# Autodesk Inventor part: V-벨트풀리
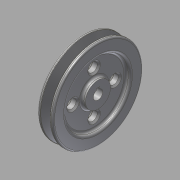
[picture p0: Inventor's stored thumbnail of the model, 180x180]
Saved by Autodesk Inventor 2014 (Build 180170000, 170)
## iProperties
Created: 2015-09
Part Number: V-벨트풀리
Material: 강철, 연강
Document SubType Name: Modeling
Designer: mduedu
Density: 1 g/cm^3
Appearance: Steel
Author: mduedu
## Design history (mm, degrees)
sketch "스케치1"
  geometry: L1 (-10, 0)-(10, 0); L2 (-10, 0)-(-10, 57.5); L3 (-10, 57.5)-(-6.062, 57.5); L4 (-6.062, 57.5)-(-2.001, 45); L5 (-2.001, 45)-(2.001, 45); L6 (2.001, 45)-(6.062, 57.5); L7 (6.062, 57.5)-(10, 57.5); L8 (10, 57.5)-(10, 0); L9 (0, 0)-(0, 45); L10 (-10, 53)-(10, 53); 3 further points
  constraints: 20 end point, 6 point on line, 3 perpendicular, 2 midpoint, 2 parallel, 2 symmetric about line, 1 coincident, 1 collinear, 1 equal length, 1 horizontal, 1 vertical, 1 vertical alignment
  dimensions: "d0" = 20 distance between parallel lines of L8 L2; "d2" = 115 diameter of L3 L1; "d5" = 8 distance between parallel lines of L5 L10; "d6" = 9.2 distance of point (4.6, 53) point (-4.6, 53); "d7" = 36 deg angle of L6 L4; "d40" = 4.5 distance between parallel lines of L10 L3
revolve "회전1" sketch "스케치1" stored, may be unused: angle "d8" = 90 deg
sketch "스케치2"
  geometry: C1 r 16 at (0, 0); C2 r 41 at (0, 0); 1 further point
  constraints: 2 centre point, 2 coincident
  dimensions: "d9" = 32 diameter of C1; "d41" = 82 diameter of C2
extrude "돌출5" cut sketch "스케치2" distance "d42" = 5; taper "d43" = 0 deg
hole "구멍2" diameter "d46" = 12; stored, may be unused: countersink angle "d50" = 90 deg, drill point angle "d52" = 118 deg; dims "d44" = 10, "d45" = 10, "d47" = 6, "d48" = 4, "d49" = 2, "d51" = 8
sketch "스케치8"
  geometry: L1 (-2, 5.657)-(2, 5.657); L2 (2, 5.657)-(2, 7.8); L3 (2, 7.8)-(-2, 7.8); L4 (-2, 7.8)-(-2, 5.657); A1 r 6 centre (0, 0) between (-2, 5.657) and (2, 5.657) reference; 1 further point
  constraints: 8 end point, 2 parallel, 2 point on circle, 1 horizontal, 1 perpendicular
  dimensions: "d53" = 4 distance of L2.end L3.end; "d55" = 13.8 dimension on A1 L3
extrude "돌출6" cut sketch "스케치8" stored distance "d56" = 5; taper "d57" = 0 deg
sketch "스케치9"
  geometry: C1 r 6 at (0, 27); 1 further point
  constraints: 1 centre point, 1 vertical alignment
  dimensions: "d61" = 12 diameter of C1; "d62" = 27 distance of C1.centre point (0, 0)
extrude "돌출7" cut sketch "스케치9" stored distance "d63" = 5; taper "d64" = 0 deg
chamfer "모따기3" distance "d65" = 2; stored, may be unused: second distance "d66" = 2, angle "d67" = 45 deg
fillet "모깎기5" dims "d71" = 2, "d72" = 1, "d73" = 0.5
fillet "모깎기6" dims "d74" = 3
fillet "모깎기7" dims "d75" = 3
fillet "모깎기8" dims "d76" = 3
sketch "스케치10"
  geometry: C1 r 47.5 at (0, 0); 1 further point
  constraints: 1 centre point, 1 coincident, 1 other
  dimensions: "d77" = 95 diameter of C1
extrude "돌출8" join sketch "스케치10" distance "d80" = 0.5; taper "d81" = 0 deg
node "솔리드1"
mirror "대칭2"
pattern_circular "원형 패턴1" dims "d69" = 360 deg
